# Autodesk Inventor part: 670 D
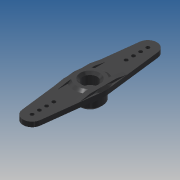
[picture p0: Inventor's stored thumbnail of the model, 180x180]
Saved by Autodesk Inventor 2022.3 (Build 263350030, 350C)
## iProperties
Created: 2021-08
Part Number: 670 D
Material: Nylon 6/6
Document SubType Name: Modeling
Designer: dotwibo2
Mass: 0.28903 g
Surface Area: 4.66998 cm^2
Volume: 0.255779 cm^3
Density: 1.13 g/cm^3
Appearance: Dark Gray
Description: SUPER STRENGTH LONG SERVO DOUBLE ARM
Vendor: DUBRO
UOFM: EACH
MAKE_OR_BUY: REF
PURCH_QTY: 0
BOM_MATL: -
Note: INCLUDED IN SET
Vendor Part No: 670 D
Alt_PN: DUBRO 670 D
Author: dotwibo2
Title: SUPER STRENGTH LONG SERVO DOUBLE ARM
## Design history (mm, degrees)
sketch "Sketch1"
  geometry: L1 (0, -7.52)-(0, 4.8) reference; L2 (1.65, -1.71)-(1.65, -2.76); L3 (1.65, -2.76)-(2.925, -2.76); L4 (2.925, -2.76)-(2.925, -5.76); L5 (2.925, -5.76)-(4.25, -5.76); L6 (5.5, -4.51)-(5.5, 0); L7 (5.5, 0)-(7.055, 0); L8 (7.055, 0)-(7.055, 2.1); L9 (7.055, 2.1)-(5.8, 3.04); L10 (5.8, 3.04)-(3.25, 3.04); L11 (-1.411, 0)-(8.466, 0) reference; L12 (1.65, -1.71)-(3.25, -1.71); L13 (3.25, -1.71)-(3.25, 3.04); L14 (5.5, -4.51)-(4.25, -5.76); 1 further point
  constraints: 25 end point, 5 horizontal, 5 vertical, 1 collinear
  dimensions: "d1" = 5.85 diameter of L4 L1; "d2" = 3.3 diameter of L2 L1; "d3" = 8.8 distance between parallel lines of L5 L10; "d7" = 11 diameter of L6 L1; "d9" = 5.76 distance between parallel lines of L7 L5; "d10" = 14.11 diameter of L8 L1; "d20" = 3 distance between parallel lines of L5 L3; "d48" = 6.5 diameter of L13 L1; "d49" = 4.75 distance between parallel lines of L10 L12; "d52" = 2.1 distance of L7.end L8.end; "d53" = 45 deg angle of L6 L14; "d54" = 8.5 diameter of L5.end L1; "d60" = 11.6 diameter of L9.end L1; "d66" = 0.94 vertical distance of L8.end L9.end (derived)
revolve "Revolution1" sketch "Sketch1" stored, may be unused: angle "d11" = 90 deg
sketch "Sketch3"
  geometry: L1 (-7.004, 0.849)-(-3.971, 25.881); L2 (3.971, 25.881)-(7.004, 0.849); L3 (9.877, 0)-(-9.877, 0) reference; L4 (0, -14.346)-(0, 36.691) reference; C1 r 7.055 at (0, 0) reference; A1 r 4 centre (0, 25.4) between (3.971, 25.881) and (-3.971, 25.881); A2 r 7.055 centre (0, 0) between (7.004, 0.849) and (-7.004, 0.849); 5 further points
  constraints: 4 end point, 4 point on circle, 3 point on line, 3 tangent, 2 centre point, 2 coincident, 1 concentric, 1 other
  dimensions: "d21" = 25.4 distance from line of L3 A1.centre; "d22" = 8 diameter of A1; "d23" = 9.525 distance of point (0, 15.875) A1.centre; "d29" = 3.175 distance of point (0, 25.4) point (0, 22.225); "d30" = 3.175 distance of point (0, 19.05) point (0, 22.225) (= d29)
extrude "Extrusion2" join sketch "Sketch3" distance "d27" = 2.1; taper "d28" = 0 deg
hole "Hole1" sketch "Sketch3" diameter "d31" = 1.5875; stored, may be unused: countersink angle "d35" = 90 deg, drill point angle "d37" = 118 deg; dims "d32" = 4, "d33" = 4, "d34" = 2, "d36" = 5
workplane "Work Plane1"
sketch "Sketch5"
  geometry: L1 (-5.265, 0)-(7.055, 0) reference; L2 (2.255, 0.849)-(2.255, -7.055) reference; L3 (2.255, 8.5)-(2.255, 0); L4 (2.255, 0)-(0.945, 0); L5 (0.945, 0)-(0.945, 4); L6 (0.945, 4)-(2.255, 8.5); L7 (5.295, 5.8)-(5.295, -5.8) reference; 1 further point
  constraints: 8 end point, 2 collinear, 2 vertical, 1 horizontal
  dimensions: "d55" = 4 distance of L4.end L5.end; "d56" = 8.5 distance from line of L1 L3.start; "d57" = 4.35 distance between parallel lines of L5 L7
extrude "Extrusion4" join sketch "Sketch5" distance "d58" = 1.72; taper "d59" = 0 deg
workplane "Work Plane2"
sketch "Sketch6"
  geometry: L1 (2.1, 25.881)-(2.1, 0.849) reference; L2 (-0.608, 0)-(3.648, 0) reference; L3 (2.1, 10.55)-(2.1, 0); L4 (2.1, 0)-(3.04, 0); L5 (3.04, 0)-(3.04, 5.8); L6 (3.04, 5.8)-(2.1, 10.55); L7 (3.04, 5.8)-(3.04, -5.8) reference; 1 further point
  constraints: 9 end point, 3 collinear, 2 vertical, 1 horizontal
  dimensions: "d62" = 5.8 distance from line of L2 L5.end; "d63" = 4.75 vertical distance of L5.end L3.start
extrude "Extrusion5" join sketch "Sketch6" distance "d64" = 2; taper "d65" = 0 deg
mirror "Mirror1"
pattern_circular "Circular Pattern3" dims "d71" = 360 deg
chamfer "Chamfer1" distance "d67" = 1; stored, may be unused: second distance "d68" = 2, angle "d69" = 45 deg
body "Solid1"
other parameters: "d61" = 5.8 (= 0.5 x d60)
